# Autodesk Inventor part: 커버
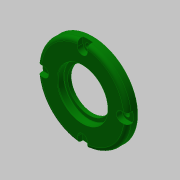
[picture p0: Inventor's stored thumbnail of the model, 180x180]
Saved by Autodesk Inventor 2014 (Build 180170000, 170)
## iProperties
Created: 2019-05
Part Number: 커버
Material: 알루미늄 6061
Document SubType Name: Modeling
Designer: mduedu
Density: 1 g/cm^3
Appearance: 진녹색
Author: mduedu
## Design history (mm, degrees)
sketch "스케치1"
  geometry: L1 (0, 0)-(36, 0); L2 (36, 0)-(36, -8); L3 (36, -8)-(0, -8); L4 (0, -8)-(0, 0); L5 (0, -8)-(26, -8); L6 (26, -8)-(26, -12); L7 (26, -12)-(0, -12); L8 (0, -12)-(0, -8)
  constraints: 16 end point, 4 parallel, 2 horizontal, 2 perpendicular
  dimensions: "d0" = 72 diameter of L2 L4; "d2" = 52 diameter of L6 L8; "d3" = 12 distance between parallel lines of L7 L1; "d4" = 4 distance between parallel lines of L7 L3
revolve "회전1" sketch "스케치1" stored, may be unused: angle "d5" = 90 deg
sketch "스케치2" dims "d6" = 62
  geometry: L1 (-4, 31)-(-4, 35.777); L2 (4, 31)-(4, 35.777); A1 r 4 centre (0, 31) between (-4, 31) and (4, 31); A2 r 36 centre (0, 0) between (-4, 35.777) and (4, 35.777) reference; A3 r 36 centre (0, 0) between (4, 35.777) and (-4, 35.777); 2 further points
  constraints: 6 point on circle, 4 end point, 2 centre point, 2 coincident, 2 tangent, 2 vertical alignment, 1 parallel, 1 vertical, 2 other
  dimensions: "d7" = 8 distance between parallel lines of L2 L1
extrude "돌출1" cut sketch "스케치2" distance "d8" = 4.4; taper "d9" = 0 deg
fillet "모깎기1" dims "d13" = 3
sketch "스케치3"
  geometry: L1 (36, -4.4)-(36, -8) reference; L2 (36, -8)-(26, -8) reference; L3 (26, -8)-(26, -12) reference; L4 (26, -12)-(-26, -12) reference; L5 (-26, -12)-(-26, -8) reference; L6 (-26, -8)-(-36, -8) reference; L7 (-36, -8)-(-36, -4.4) reference; L8 (-36, -4.4)-(-27, -4.4) reference; L9 (-27, -4.4)-(-27, 0) reference; L10 (-27, 0)-(27, 0) reference; L11 (27, 0)-(27, -4.4) reference; L12 (27, -4.4)-(36, -4.4) reference; L13 (0, 0)-(20, 0); L14 (20, 0)-(20, -5.2); L15 (20, -5.2)-(0, -5.2); L16 (0, -5.2)-(0, 0); L17 (0, -5.2)-(17, -5.2); L18 (17, -5.2)-(17, -8); L19 (17, -8)-(0, -8); L20 (0, -8)-(0, -5.2); L21 (0, -8)-(23, -8); L22 (23, -8)-(23, -12); L23 (23, -12)-(0, -12); L24 (0, -12)-(0, -8)
  constraints: 24 end point, 6 parallel, 3 horizontal, 3 perpendicular, 1 point on line
  dimensions: "d14" = 40 diameter of L14 L16; "d16" = 5.2 distance of L13.end L14.end; "d17" = 46 diameter of L22 L24; "d18" = 4 distance of L21.end L22.end; "d19" = 34 diameter of L18 L20
revolve "회전2" sketch "스케치3" stored, may be unused: angle "d20" = 90 deg
chamfer "모따기1" distance "d21" = 0.5; stored, may be unused: second distance "d22" = 2, angle "d23" = 30 deg
fillet "모깎기2" dims "d24" = 0.2
fillet "모깎기3" dims "d25" = 3
chamfer "모따기2" distance "d26" = 1; stored, may be unused: second distance "d27" = 2, angle "d28" = 30 deg
sketch "스케치4" dims "d29" = 62
  geometry: 6 further points
  constraints: 2 vertical alignment, 1 coincident, 7 other
  dimensions: "d32" = 360 deg dimension on point (0, 0) point (0, 31) (derived)
sketch "스케치5"
  geometry: 4 further points
  constraints: 4 other
hole "구멍1" sketch "스케치5" at (-31, 0), (0, -31), (31, 0), (0, 31) diameter "d34" = 4.5; stored, may be unused: countersink angle "d38" = 90 deg, drill point angle "d40" = 0 deg; dims "d35" = 6, "d36" = 4, "d37" = 2, "d39" = 8
node "솔리드1"
pattern_circular "원형 패턴1" dims angle "d11" = 360 deg
node "절단 모서리 투영1"
